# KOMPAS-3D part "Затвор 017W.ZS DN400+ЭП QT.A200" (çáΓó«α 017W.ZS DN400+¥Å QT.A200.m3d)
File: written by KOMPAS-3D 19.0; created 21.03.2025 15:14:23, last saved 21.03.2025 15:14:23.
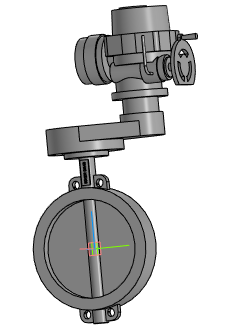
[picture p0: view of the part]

Document properties: Полное имя файла: Затвор 017W.ZS DN400+ЭП QT.A200.a3d

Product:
- Part/product: Затвор 017W.ZS DN400+ЭП QT.A200
    Масса: 318.34

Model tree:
1. Операция без истории:1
